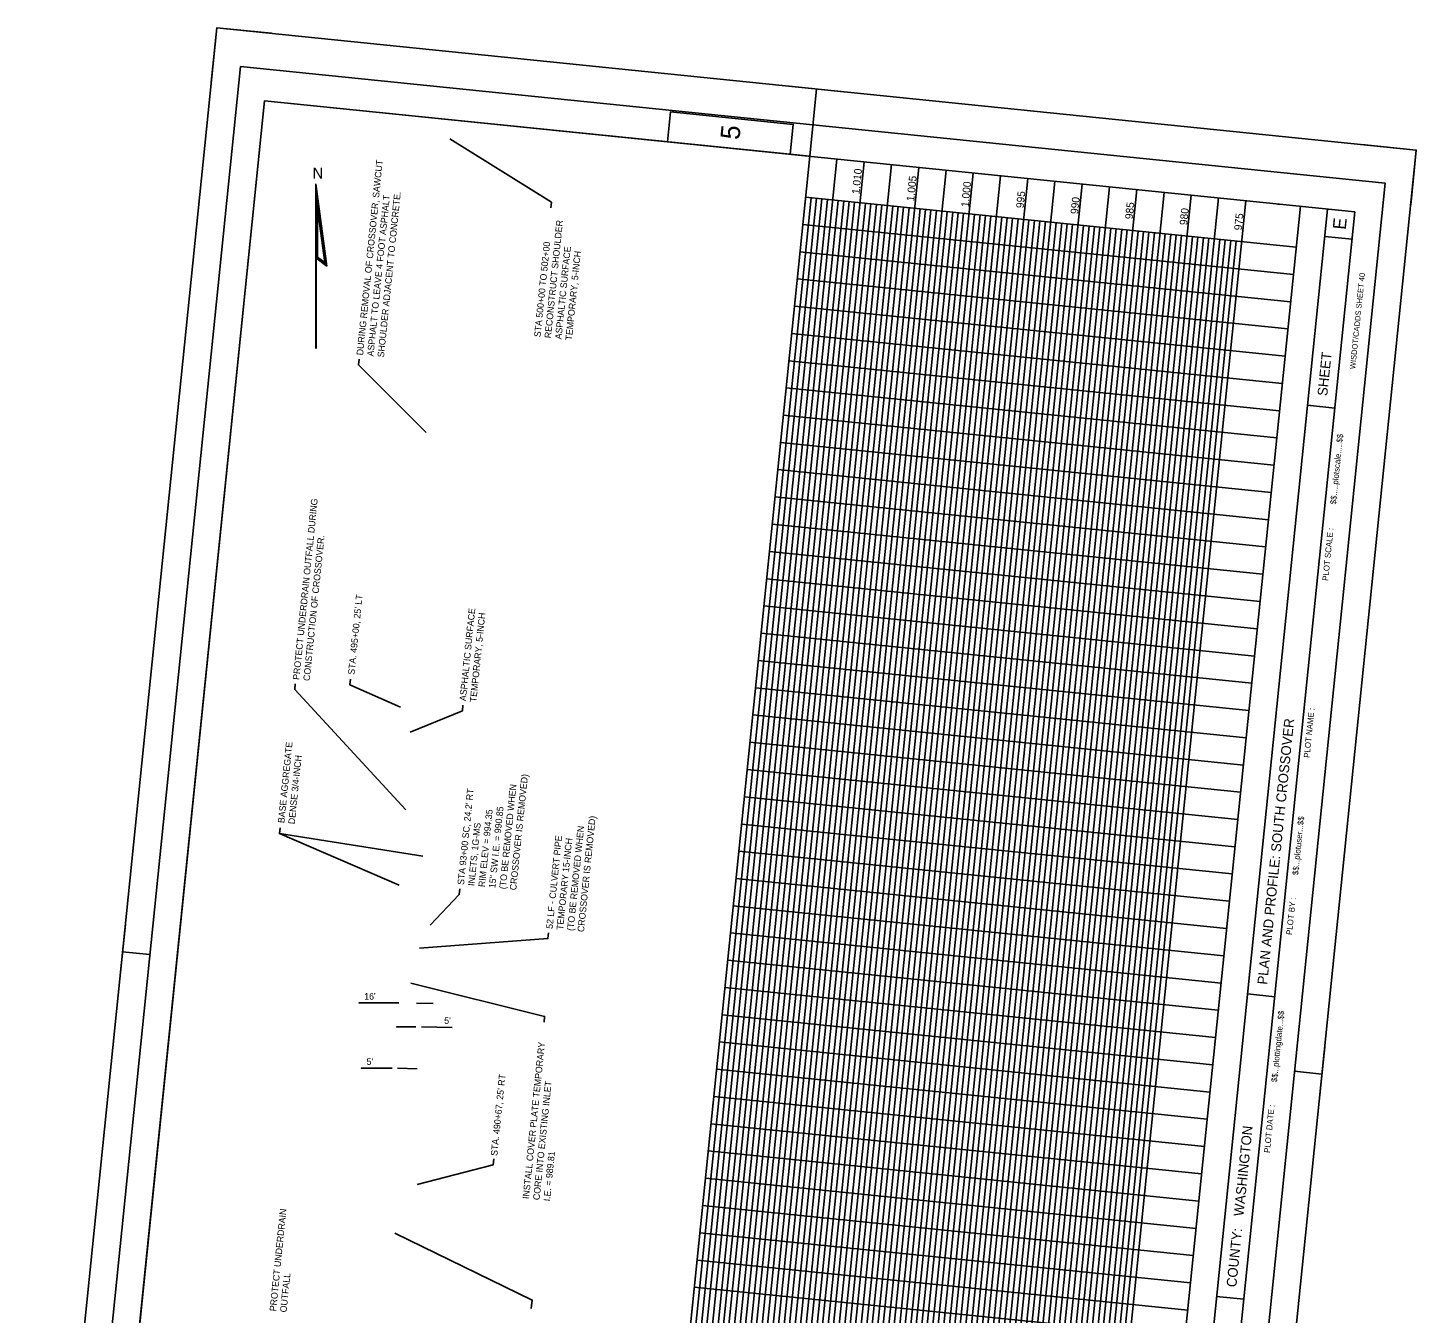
# Model space of a CAD drawing. Extents: x 359697 to 360964, y 172658 to 174461.
# Drawn here: x 359697 to 360964, y 173287 to 174461 of the extents above; entities that cross this region are included whole.
import ezdxf

# ---------------------------------------------------------------- set-up
doc = ezdxf.new("R2010")
doc.units = 0
for name, color, linetype in [('Default', 7, 'Continuous'), ('E_PROF_Grid', 7, 'Continuous'), ('E_PROF_GridMin', 7, 'Continuous'), ('P_MISC', 7, 'Continuous'), ('P_MISC_TXT', 7, 'Continuous'), ('P_RDWY_Text', 7, 'Continuous'), ('PLT_Sheet_Border', 7, 'Continuous'), ('PLT_Sheet_Info', 7, 'Continuous')]:
    doc.layers.add(name, color=color, linetype=linetype)

msp = doc.modelspace()

# ---------------------------------------------------------------- linework, layer by layer
at = {"layer": 'Default'}
msp.add_lwpolyline([(359753, 172827.2), (360250.4, 172776.4), (360410.3, 174343.3), (359912.9, 174394)], close=True, dxfattribs=at)
at = {"layer": 'E_PROF_Grid'}
for p, q in [((360250.4, 172776.4), (360410.3, 174343.3)), ((360275.3, 172773.9), (360435.2, 174340.7)), ((360300.1, 172771.3), (360460.1, 174338.2)), ((360325, 172768.8), (360484.9, 174335.7)), ((360349.9, 172766.3), (360509.8, 174333.1)), ((360374.8, 172763.7), (360534.7, 174330.6)), ((360399.6, 172761.2), (360559.5, 174328)), ((360424.5, 172758.7), (360584.4, 174325.5)), ((360449.4, 172756.1), (360609.3, 174323)), ((360474.2, 172753.6), (360634.1, 174320.4)), ((360499.1, 172751), (360659, 174317.9)), ((360524, 172748.5), (360683.9, 174315.4)), ((360854.2, 174260.3), (360406.5, 174306)), ((360548.9, 172746), (360708.8, 174312.8)), ((360573.7, 172743.4), (360733.6, 174310.3)), ((360598.6, 172740.9), (360758.5, 174307.7)), ((360623.5, 172738.3), (360783.4, 174305.2)), ((360648.3, 172735.8), (360808.2, 174302.7)), ((360698.1, 172730.7), (360858, 174297.6)), ((360851.6, 174235.4), (360404, 174281.1)), ((360849.1, 174210.5), (360401.4, 174256.2)), ((360846.6, 174185.7), (360398.9, 174231.4)), ((360844, 174160.8), (360396.3, 174206.5)), ((360841.5, 174135.9), (360393.8, 174181.6)), ((360838.9, 174111.1), (360391.3, 174156.7)), ((360836.4, 174086.2), (360388.7, 174131.9)), ((360833.9, 174061.3), (360386.2, 174107)), ((360831.3, 174036.4), (360383.7, 174082.1)), ((360828.8, 174011.6), (360381.1, 174057.3)), ((360826.3, 173986.7), (360378.6, 174032.4)), ((360823.7, 173961.8), (360376, 174007.5)), ((360821.2, 173937), (360373.5, 173982.7)), ((360818.6, 173912.1), (360371, 173957.8)), ((360816.1, 173887.2), (360368.4, 173932.9)), ((360813.6, 173862.4), (360365.9, 173908)), ((360811, 173837.5), (360363.4, 173883.2)), ((360808.5, 173812.6), (360360.8, 173858.3)), ((360806, 173787.7), (360358.3, 173833.4)), ((360803.4, 173762.9), (360355.7, 173808.6)), ((360800.9, 173738), (360353.2, 173783.7)), ((360798.3, 173713.1), (360350.7, 173758.8)), ((360795.8, 173688.3), (360348.1, 173733.9)), ((360793.3, 173663.4), (360345.6, 173709.1)), ((360790.7, 173638.5), (360343, 173684.2)), ((360788.2, 173613.6), (360340.5, 173659.3)), ((360785.6, 173588.8), (360338, 173634.5)), ((360783.1, 173563.9), (360335.4, 173609.6)), ((360780.6, 173539), (360332.9, 173584.7)), ((360778, 173514.2), (360330.4, 173559.8)), ((360775.5, 173489.3), (360327.8, 173535)), ((360773, 173464.4), (360325.3, 173510.1)), ((360770.4, 173439.5), (360322.7, 173485.2)), ((360767.9, 173414.7), (360320.2, 173460.4)), ((360765.3, 173389.8), (360317.7, 173435.5)), ((360762.8, 173364.9), (360315.1, 173410.6)), ((360760.3, 173340.1), (360312.6, 173385.8)), ((360757.7, 173315.2), (360310.1, 173360.9)), ((360755.2, 173290.3), (360307.5, 173336)), ((360752.6, 173265.5), (360305, 173311.1))]:
    msp.add_line(p, q, dxfattribs=at)
at = {"layer": 'E_PROF_GridMin'}
for p, q in [((360259.2, 172813.2), (360411.5, 174305.4)), ((360264.2, 172812.7), (360416.4, 174304.9)), ((360269.1, 172812.2), (360421.4, 174304.4)), ((360274.1, 172811.6), (360426.4, 174303.9)), ((360284.1, 172810.6), (360436.3, 174302.9)), ((360289, 172810.1), (360441.3, 174302.4)), ((360294, 172809.6), (360446.3, 174301.9)), ((360299, 172809.1), (360451.3, 174301.4)), ((360308.9, 172808.1), (360461.2, 174300.3)), ((360313.9, 172807.6), (360466.2, 174299.8)), ((360318.9, 172807.1), (360471.2, 174299.3)), ((360323.8, 172806.6), (360476.1, 174298.8)), ((360333.8, 172805.6), (360486.1, 174297.8)), ((360338.8, 172805), (360491.1, 174297.3)), ((360343.7, 172804.5), (360496, 174296.8)), ((360348.7, 172804), (360501, 174296.3)), ((360358.7, 172803), (360511, 174295.3)), ((360363.6, 172802.5), (360515.9, 174294.8)), ((360368.6, 172802), (360520.9, 174294.2)), ((360373.6, 172801.5), (360525.9, 174293.7)), ((360383.5, 172800.5), (360535.8, 174292.7)), ((360388.5, 172800), (360540.8, 174292.2)), ((360393.5, 172799.5), (360545.8, 174291.7)), ((360398.5, 172799), (360550.7, 174291.2)), ((360408.4, 172797.9), (360560.7, 174290.2)), ((360413.4, 172797.4), (360565.7, 174289.7)), ((360418.4, 172796.9), (360570.6, 174289.2)), ((360423.3, 172796.4), (360575.6, 174288.7)), ((360433.3, 172795.4), (360585.6, 174287.6)), ((360438.2, 172794.9), (360590.5, 174287.1)), ((360443.2, 172794.4), (360595.5, 174286.6)), ((360448.2, 172793.9), (360600.5, 174286.1)), ((360458.1, 172792.9), (360610.4, 174285.1)), ((360463.1, 172792.4), (360615.4, 174284.6)), ((360468.1, 172791.8), (360620.4, 174284.1)), ((360473.1, 172791.3), (360625.4, 174283.6)), ((360483, 172790.3), (360635.3, 174282.6)), ((360488, 172789.8), (360640.3, 174282.1)), ((360493, 172789.3), (360645.3, 174281.6)), ((360497.9, 172788.8), (360650.2, 174281)), ((360507.9, 172787.8), (360660.2, 174280)), ((360512.9, 172787.3), (360665.2, 174279.5)), ((360517.8, 172786.8), (360670.1, 174279)), ((360522.8, 172786.3), (360675.1, 174278.5)), ((360532.8, 172785.2), (360685.1, 174277.5)), ((360537.7, 172784.7), (360690, 174277)), ((360542.7, 172784.2), (360695, 174276.5)), ((360547.7, 172783.7), (360700, 174276)), ((360557.6, 172782.7), (360709.9, 174275)), ((360562.6, 172782.2), (360714.9, 174274.4)), ((360567.6, 172781.7), (360719.9, 174273.9)), ((360572.6, 172781.2), (360724.8, 174273.4)), ((360582.5, 172780.2), (360734.8, 174272.4)), ((360587.5, 172779.7), (360739.8, 174271.9)), ((360592.4, 172779.2), (360744.7, 174271.4)), ((360597.4, 172778.6), (360749.7, 174270.9)), ((360607.4, 172777.6), (360759.7, 174269.9)), ((360612.3, 172777.1), (360764.6, 174269.4)), ((360617.3, 172776.6), (360769.6, 174268.9)), ((360622.3, 172776.1), (360774.6, 174268.4)), ((360632.2, 172775.1), (360784.5, 174267.3)), ((360637.2, 172774.6), (360789.5, 174266.8)), ((360642.2, 172774.1), (360794.5, 174266.3)), ((360647.2, 172773.6), (360799.5, 174265.8))]:
    msp.add_line(p, q, dxfattribs=at)
at = {"layer": 'P_MISC'}
for p, q in [((359969.8, 174243), (359959.8, 174318)), ((359959.8, 174250.5), (359959.8, 174318)), ((359960.6, 174250.9), (359960.6, 174306.7)), ((359968.8, 174244.7), (359960.6, 174306.7)), ((359961.3, 174251.2), (359961.3, 174295.4)), ((359967.9, 174246.3), (359961.3, 174295.4)), ((359959.8, 174250.5), (359969.8, 174243)), ((359959.8, 174168), (359959.8, 174250.5)), ((359960.1, 174168), (359960.1, 174250.3)), ((359960.6, 174250.9), (359968.8, 174244.7)), ((359961.3, 174251.2), (359967.9, 174246.3))]:
    msp.add_line(p, q, dxfattribs=at)
msp.add_lwpolyline([(359959.8, 174317.9), (359959.8, 174317.9)], dxfattribs=at)
at = {"layer": 'P_MISC_TXT'}
for p, q in [((360051.5, 173570.3), (360066.8, 173570)), ((360056, 173548.8), (360084.2, 173548.2)), ((360034.2, 173511), (360052.2, 173510.6))]:
    msp.add_line(p, q, dxfattribs=at)
for points in [[(360081.8, 174359.1), (360174.6, 174301.3), (360174, 174296.1)], [(360060.4, 174091.1), (359998.6, 174152.9), (359999.1, 174158)], [(360041.9, 173746.8), (359940.4, 173856.6), (359940.9, 173861.8)], [(360037, 173840.4), (359990.8, 173860.8), (359991.2, 173866)], [(360045.6, 173817.7), (360093.4, 173837.2), (360093.9, 173842.4)], [(360057.2, 173704.7), (359926.5, 173725.1), (359927, 173730.3)], [(360035.7, 173678), (359926.5, 173725.1), (359927, 173730.3)], [(360064.1, 173641.7), (360090.6, 173669.5), (360091.1, 173674.6)], [(360054.4, 173620.5), (360171.5, 173629.4), (360172, 173634.6)], [(360046.4, 173588.6), (360168.4, 173558.3), (360167.9, 173553.1)], [(360035.5, 173570.6), (359999, 173570.6), (360035.5, 173570.6)], [(360051, 173548.8), (360033.4, 173548.8), (360051, 173548.8)], [(360029.2, 173511.1), (360001.1, 173511.1), (360029.2, 173511.1)], [(360052.1, 173404.8), (360121.6, 173423), (360122.1, 173428.2)], [(360031.7, 173360.5), (360157.2, 173299.4), (360156.3, 173291.8)]]:
    msp.add_lwpolyline(points, dxfattribs=at)
at = {"layer": 'P_RDWY_Text'}
msp.add_lwpolyline([(359696.8, 172769.3), (359869.4, 174460.6), (360963.7, 174348.9), (360791.1, 172657.7)], close=True, dxfattribs=at)
at = {"layer": 'PLT_Sheet_Border'}
for points in [[(360791.1, 172657.7), (360963.7, 174348.9), (359869.4, 174460.6), (359696.8, 172769.3)], [(360767.5, 172672.1), (360935.5, 174318.6), (359890.9, 174425.2), (359722.9, 172778.7)]]:
    msp.add_lwpolyline(points, close=True, dxfattribs=at)
at = {"layer": 'PLT_Sheet_Info'}
for p, q in [((359864.3, 174410.8), (359869.4, 174460.6)), ((359919.2, 174455.5), (359869.4, 174460.6)), ((360441.4, 174402.2), (360391.7, 174407.2)), ((360416.6, 174404.7), (360410.3, 174343.3)), ((359753, 172827.2), (359912.9, 174394)), ((360907.7, 174292.5), (359912.9, 174394)), ((360963.7, 174348.9), (360914, 174353.9)), ((360958.7, 174299.1), (360963.7, 174348.9)), ((360722.9, 172728.2), (360882.9, 174295.1)), ((360747.8, 172725.7), (360907.7, 174292.5)), ((360838, 174299.1), (360838.1, 174299.6)), ((360905.2, 174267.6), (360880.3, 174270.2)), ((360889.5, 174113.4), (360864.6, 174116)), ((359780.8, 173592.6), (359785.9, 173642.3)), ((359783.4, 173617.4), (359808.2, 173614.9)), ((360834.6, 173576.2), (360809.8, 173578.8)), ((360875.2, 173480.9), (360880.2, 173530.6)), ((360877.7, 173505.7), (360852.8, 173508.3)), ((360806.5, 173300.2), (360781.6, 173302.7))]:
    msp.add_line(p, q, dxfattribs=at)
msp.add_lwpolyline([(360280.6, 174356.5), (360283.4, 174383.9), (360395.3, 174372.4), (360392.5, 174345.1)], close=True, dxfattribs=at)

# ---------------------------------------------------------------- texts
at = {"layer": 'P_MISC'}
msp.add_text('N', height=10, dxfattribs=at).set_placement((359956.7, 174322.9))
at = {"layer": 'P_MISC_TXT'}
for s, height, rotation, p in [('DURING REMOVAL OF CROSSOVER, SAWCUT', 6, 84.1825, (360002.7, 174161.4)), ('1,010', 7, 84.1728, (360455.7, 174308.4)), ('1,005', 7, 84.1728, (360505.6, 174301.9)), ('1,000', 7, 84.1728, (360555.3, 174296.6)), ('ASPHALT TO LEAVE 4 FOOT ASPHALT', 6, 84.1825, (360012.3, 174160.4)), ('SHOULDER ADJACENT TO CONCRETE.', 6, 84.1825, (360021.8, 174159.5)), ('995', 7, 84.1728, (360605.5, 174295.6)), ('990', 7, 84.1728, (360655.2, 174290.2)), ('985', 7, 84.1728, (360705, 174285.5)), ('980', 7, 84.1728, (360754.7, 174280.1)), ('975', 7, 84.1728, (360804.5, 174275.4)), ('RECONSTRUCT SHOULDER', 6, 84.1728, (360174.2, 174177)), ('STA 500+00 TO 502+00', 6, 84.1728, (360164.7, 174178)), ('ASPHALTIC SURFACE', 6, 84.1728, (360183.8, 174176)), ('TEMPORARY, 5-INCH', 6, 84.1728, (360193.3, 174175)), ('PROTECT UNDERDRAIN OUTFALL DURING', 6, 84.1825, (359944.6, 173865.2)), ('CONSTRUCTION OF CROSSOVER.', 6, 84.1825, (359954.1, 173864.2)), ("STA. 495+00, 25' LT", 6, 84.1728, (359994.9, 173869.9)), ('ASPHALTIC SURFACE', 6, 84.1728, (360096.6, 173845.9)), ('TEMPORARY, 5-INCH', 6, 84.1728, (360106.1, 173844.9)), ('BASE AGGREGATE', 6, 84.1728, (359930.9, 173734.5)), ('DENSE 3/4-INCH', 6, 84.1728, (359940.4, 173733.5)), ('(TO BE REMOVED WHEN', 6, 84.1825, (360133, 173674.2)), ('CROSSOVER IS REMOVED)', 6, 84.1825, (360142.5, 173673.2)), ("STA 93+00 SC, 24.2' RT", 6, 84.1825, (360094.8, 173678.1)), ('RIM ELEV = 994.35', 6, 84.1825, (360113.9, 173676.1)), ('15" SW I.E. = 990.85', 6, 84.1825, (360123.4, 173675.1)), ('INLETS, 1G-MS', 6, 84.1825, (360104.3, 173677.1)), ('CROSSOVER IS REMOVED)', 6, 84.1825, (360204.3, 173635.1)), ('52 LF - CULVERT PIPE', 6, 84.1825, (360175.7, 173638)), ('TEMPORARY 15-INCH', 6, 84.1825, (360185.2, 173637)), ('(TO BE REMOVED WHEN', 6, 84.1825, (360194.8, 173636.1)), ("16'", 6, 359.9949, (360003.8, 173573.6)), ("5'", 6, 359.9949, (360076.8, 173551.5)), ('INSTALL COVER PLATE TEMPORARY', 6, 84.1825, (360154.2, 173391.4)), ("5'", 6, 359.9949, (360005.9, 173514.1)), ("STA. 490+67, 25' RT", 6, 84.1728, (360125.2, 173430.8)), ('CORE INTO EXISTING INLET', 6, 84.1825, (360163.8, 173390.4)), ('I.E. = 989.81', 6, 84.1825, (360173.3, 173389.4)), ('PROTECT UNDERDRAIN', 6, 84.1825, (359923.4, 173289)), ('OUTFALL', 6, 84.1825, (359932.9, 173288))]:
    msp.add_text(s, height=height, rotation=rotation, dxfattribs=at).set_placement(p)
at = {"layer": 'PLT_Sheet_Info'}
for s, height, p in [('5', 17.5, (360346.1, 174357.8)), ('E', 12, (360899.4, 174275.9)), ('WISDOT/CADDS SHEET 40', 5, (360908.1, 174148.8)), ('SHEET ', 9, (360882.5, 174124.2)), ('$$.....plotscale.....$$', 5.4, (360890.5, 174025.4)), ('PLOT SCALE : ', 5.4, (360883.4, 173955.6)), ('PLOT NAME :                      ', 5.4, (360866.4, 173794.1)), ('PLAN AND PROFILE: SOUTH CROSSOVER', 9, (360827.7, 173587)), ('$$...plotuser...$$', 5.4, (360856, 173687.1)), ('PLOT BY :', 5.4, (360850.4, 173632.4)), ('$$...plottingdate...$$', 5.4, (360836.7, 173498.1)), ('PLOT DATE :', 5.4, (360830.1, 173433.5)), ('WASHINGTON', 9, (360806.1, 173375.6)), ('COUNTY:', 9, (360799.5, 173310.9))]:
    msp.add_text(s, height=height, rotation=84.1728, dxfattribs=at).set_placement(p)

doc.saveas('drawing.dxf')
